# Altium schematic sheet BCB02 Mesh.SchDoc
size A4; Revision: V1.0; SheetNumber: 1; SheetTotal: 1
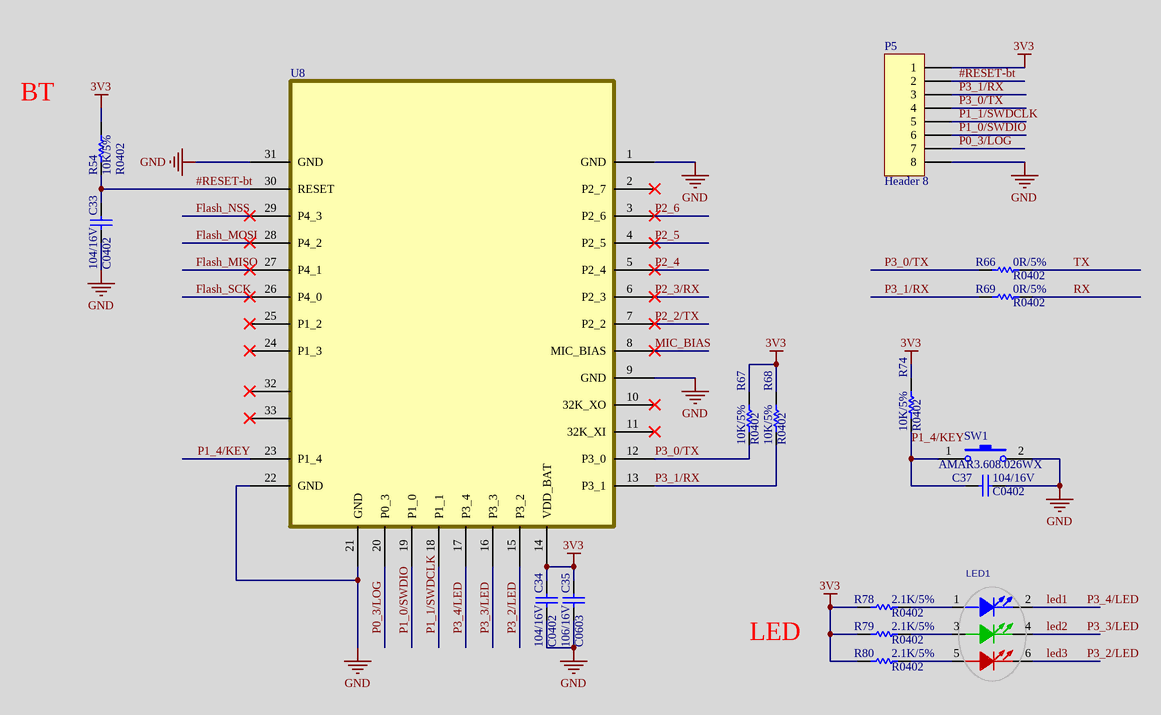
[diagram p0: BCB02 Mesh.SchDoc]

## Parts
C33  104/16V  [C0402]
C34  104/16V  [C0402]
C35  106/16V  [C0603]
C37  104/16V  [C0402]
LED1  RED/BLUE/BLUE  [直角LED_4]  (value not drawn)
P5  Header 8  [HDR1X8]
R54  10K/5%  [R0402]
R66  0R/5%  [R0402]
R67  10K/5%  [R0402]
R68  10K/5%  [R0402]
R69  0R/5%  [R0402]
R74  10K/5%  [R0402]
R78  2.1K/5%  [R0402]
R79  2.1K/5%  [R0402]
R80  2.1K/5%  [R0402]
SW1  AMAR3.608.026WX  [3PIN 4.5*4.5*4.3MM 侧按开关]
U8  BCB01  [Bluetooth]  (value not drawn)

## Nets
3V3: C34.2 C35.2 P5.1 R54.2 R67.2 R68.2 R74.2 R78.1 R79.1 R80.1 U8.14(VDD_BAT)
GND: C33.1 C34.1 C35.1 C37.2 P5.8 SW1.2 U8.1(GND) U8.9(GND) U8.21(GND) U8.22(GND) U8.31(GND)
#RESET-bt: C33.2 P5.2 R54.1 U8.30(RESET)
Flash_MISO: U8.27(P4_1)
Flash_MOSI: U8.28(P4_2)
Flash_NSS: U8.29(P4_3)
Flash_SCK: U8.26(P4_0)
led1: LED1.2(CATHODE) U8.17(P3_4)  [also labelled P3_4/LED]
led2: LED1.4(ANODE) U8.16(P3_3)  [also labelled P3_3/LED]
led3: LED1.6(CATHODE) U8.15(P3_2)  [also labelled P3_2/LED]
MIC_BIAS: U8.8(MIC_BIAS)
P0_3/LOG: P5.7 U8.20(P0_3)
P1_0/SWDIO: P5.6 U8.19(P1_0)
P1_1/SWDCLK: P5.5 U8.18(P1_1)
P1_4/KEY: C37.1 R74.1 SW1.1 U8.23(P1_4)
P2_2/TX: U8.7(P2_2)
P2_3/RX: U8.6(P2_3)
P2_4: U8.5(P2_4)
P2_5: U8.4(P2_5)
P2_6: U8.3(P2_6)
P3_0/TX: P5.4 R66.1 R67.1 U8.12(P3_0)
P3_1/RX: P5.3 R68.1 R69.1 U8.13(P3_1)
RX: R69.2
TX: R66.2
NetLED1_1: LED1.1(ANODE) R78.2
NetLED1_3: LED1.3(ANODE) R79.2
NetLED1_5: LED1.5(ANODE) R80.2

Not connected (* = marked no-connect by the designer): U8 2(P2_7)* 10(32K_XO)* 11(32K_XI)* 24(P1_3)* 25(P1_2)* 32* 33*

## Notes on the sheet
- BT
- LED

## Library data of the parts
C33-C35 C37 = Cap: Capacitor
LED1 = LED_3
P5 = Header 8: Header, 8-Pin
R54 R66-R69 R74 R78-R80 = Res: Resistor
SW1 = SW-PB: Switch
